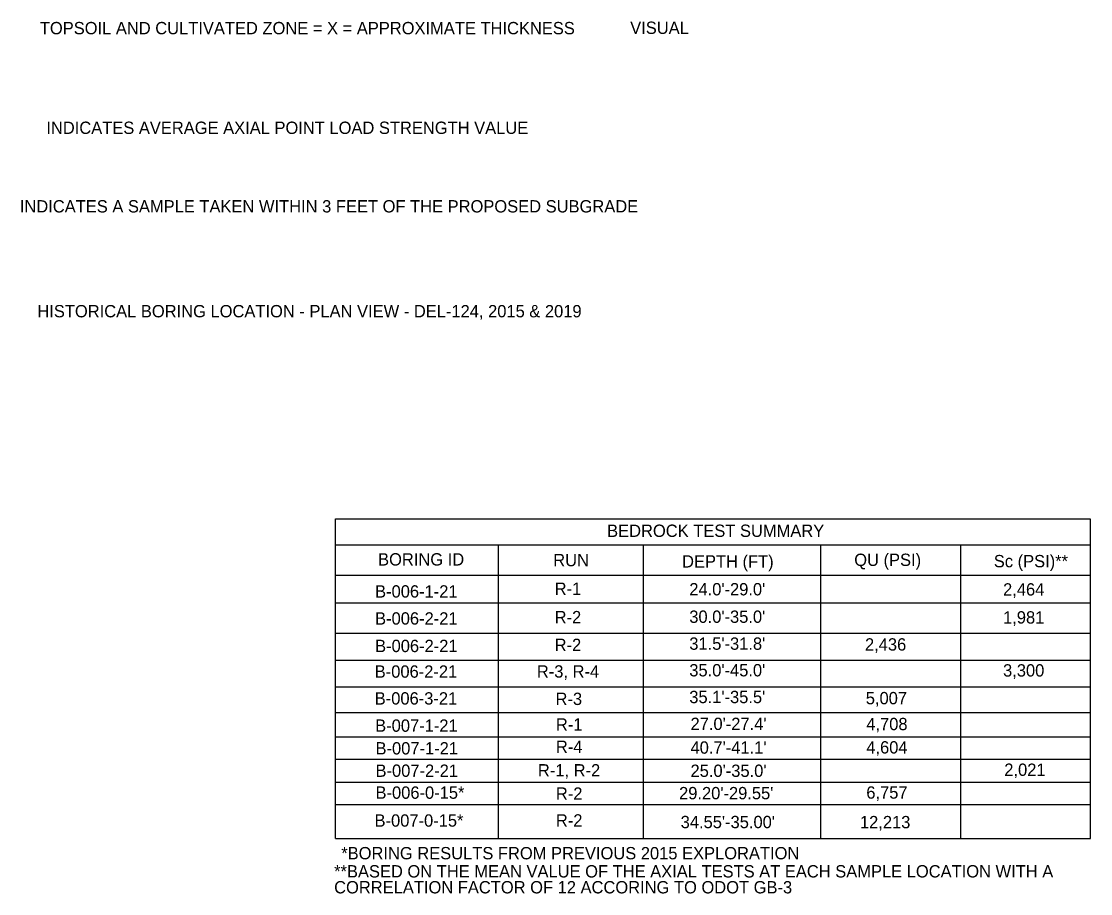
# Model space of a CAD drawing. Extents: x -5.4 to 49.9, y 13.2 to 48.4.
# Drawn here: x 14.07 to 26.21, y 13.39 to 23.3 of the extents above; entities that cross this region are included whole.
import ezdxf

# ---------------------------------------------------------------- set-up
doc = ezdxf.new("R2010")
doc.units = 0
doc.layers.add('SH_Data', color=7, linetype='Continuous')
doc.layers.add('SH_Text', color=7, linetype='Continuous')

msp = doc.modelspace()

# ---------------------------------------------------------------- linework, layer by layer
at = {"layer": 'SH_Data'}
for p, q in [((17.635, 14.016), (17.635, 17.648)), ((17.635, 17.648), (26.209, 17.648)), ((26.209, 14.016), (26.209, 17.646)), ((17.635, 17.355), (26.209, 17.355)), ((19.484, 14.016), (19.484, 17.353)), ((21.131, 14.016), (21.131, 17.355)), ((23.147, 14.016), (23.147, 17.348)), ((24.734, 14.016), (24.734, 17.351)), ((17.635, 17.008), (26.209, 17.008)), ((17.635, 16.694), (26.209, 16.694)), ((17.635, 16.35), (26.209, 16.35)), ((17.635, 16.042), (26.209, 16.042)), ((17.635, 15.74), (26.209, 15.74)), ((17.635, 15.447), (26.209, 15.447)), ((17.635, 15.172), (26.209, 15.172)), ((17.635, 14.919), (26.209, 14.919)), ((17.635, 14.656), (26.209, 14.656)), ((17.635, 14.402), (26.209, 14.402)), ((17.635, 14.016), (26.209, 14.016))]:
    msp.add_line(p, q, dxfattribs=at)

# ---------------------------------------------------------------- texts
at = {"layer": 'SH_Text'}
for s, p in [('TOPSOIL AND CULTIVATED ZONE = X = APPROXIMATE THICKNESS', (14.277, 23.152)), ('VISUAL ', (20.981, 23.156)), ('INDICATES AVERAGE AXIAL POINT LOAD STRENGTH VALUE', (14.351, 22.02)), ('INDICATES A SAMPLE TAKEN WITHIN 3 FEET OF THE PROPOSED SUBGRADE', (14.05, 21.128)), ('HISTORICAL BORING LOCATION - PLAN VIEW - DEL-124, 2015 & 2019', (14.249, 19.937)), ('BEDROCK TEST SUMMARY', (20.719, 17.443)), ('BORING ID', (18.118, 17.118)), ('RUN', (20.107, 17.11)), ('DEPTH (FT)', (21.57, 17.095)), ('QU (PSI)', (23.525, 17.113)), ('Sc (PSI)**', (25.11, 17.098)), ('B-006-1-21', (18.084, 16.754)), ('R-1', (20.123, 16.785)), ("24.0'-29.0'", (21.652, 16.779)), ('2,464', (25.215, 16.777)), ('B-006-2-21', (18.084, 16.447)), ('R-2', (20.123, 16.462)), ("30.0'-35.0'", (21.652, 16.467)), ('1,981', (25.215, 16.459)), ('B-006-2-21', (18.084, 16.135)), ('R-2', (20.123, 16.147)), ("31.5'-31.8'", (21.652, 16.161)), ('2,436', (23.647, 16.152)), ('B-006-2-21', (18.08, 15.844)), ('R-3, R-4', (19.921, 15.845)), ("35.0'-45.0'", (21.652, 15.859)), ('3,300', (25.215, 15.857)), ('B-006-3-21', (18.08, 15.539)), ('R-3', (20.133, 15.534)), ("35.1'-35.5'", (21.652, 15.555)), ('5,007', (23.656, 15.542)), ('B-007-1-21', (18.085, 15.23)), ('R-1', (20.137, 15.243)), ("27.0'-27.4'", (21.666, 15.25)), ('4,708', (23.662, 15.248)), ('B-007-1-21', (18.089, 14.972)), ('R-4', (20.137, 14.99)), ("40.7'-41.1'", (21.666, 14.981)), ('4,604', (23.662, 14.983)), ('B-007-2-21', (18.089, 14.718)), ('R-1, R-2', (19.933, 14.722)), ("25.0'-35.0'", (21.666, 14.717)), ('2,021', (25.229, 14.729)), ('B-006-0-15*', (18.089, 14.469)), ('R-2', (20.137, 14.458)), ("29.20'-29.55'", (21.536, 14.463)), ('6,757', (23.662, 14.47)), ('B-007-0-15*', (18.078, 14.152)), ('R-2', (20.137, 14.153)), ("34.55'-35.00'", (21.554, 14.135)), ('12,213', (23.59, 14.134)), ('*BORING RESULTS FROM PREVIOUS 2015 EXPLORATION', (17.7, 13.781)), ('**BASED ON THE MEAN VALUE OF THE AXIAL TESTS AT EACH SAMPLE LOCATION WITH A ', (17.619, 13.575)), ('CORRELATION FACTOR OF 12 ACCORING TO ODOT GB-3', (17.619, 13.394))]:
    msp.add_text(s, height=0.14, dxfattribs=at).set_placement(p)

doc.saveas('drawing.dxf')
